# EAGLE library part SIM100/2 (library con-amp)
AMP connector
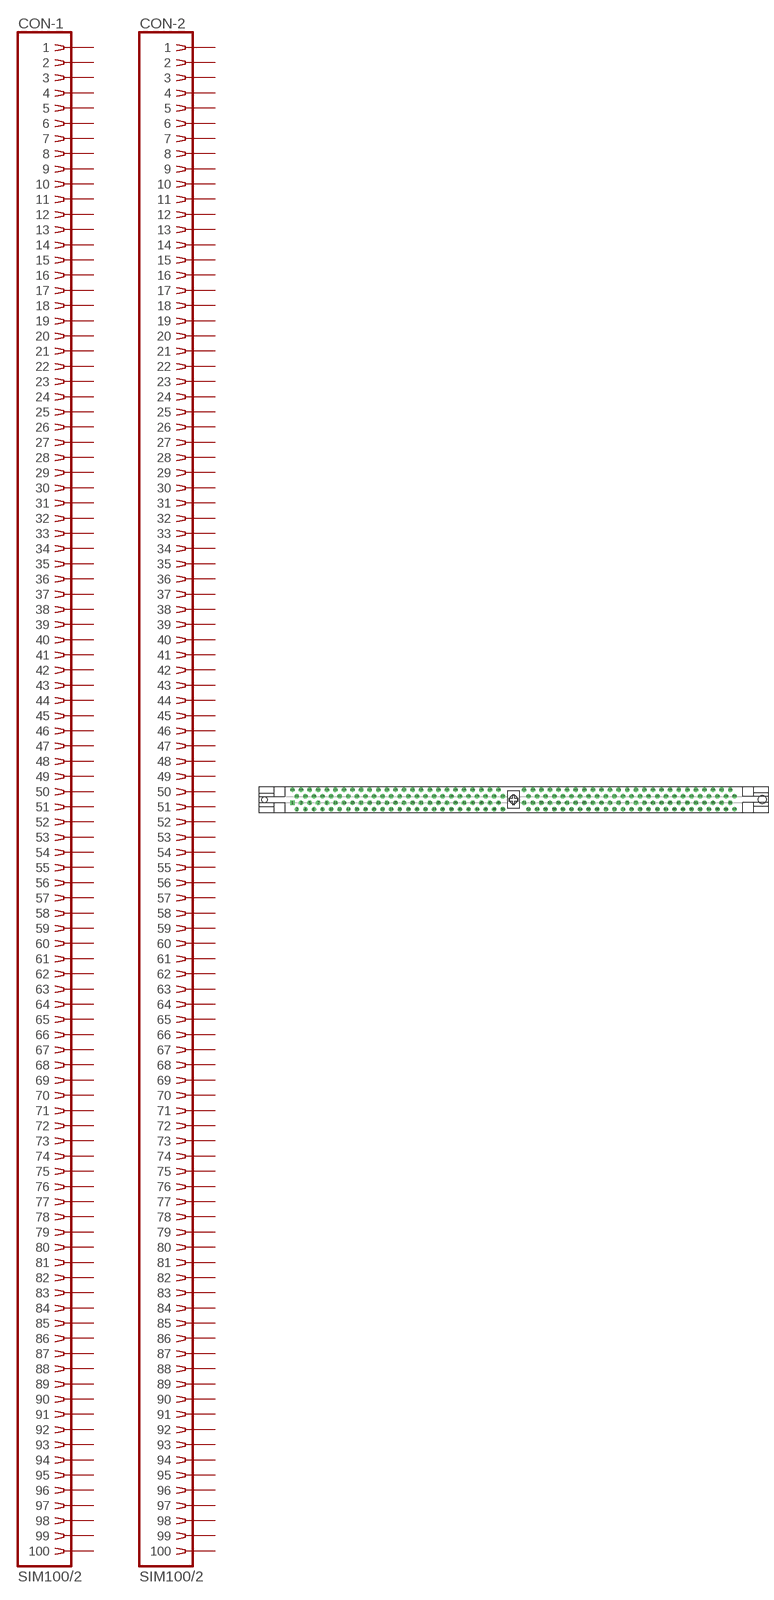
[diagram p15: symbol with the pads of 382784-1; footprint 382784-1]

Designator prefix CON; gates -1=SIMM100 -2=SIMM100

## SIM100/2 (OC_FARNELL: unknown; OC_NEWARK: unknown)  [382784-1]
1  -1:1  pas
2  -1:2  pas
3  -1:3  pas
4  -1:4  pas
5  -1:5  pas
6  -1:6  pas
7  -1:7  pas
8  -1:8  pas
9  -1:9  pas
10  -1:10  pas
11  -1:11  pas
12  -1:12  pas
13  -1:13  pas
14  -1:14  pas
15  -1:15  pas
16  -1:16  pas
17  -1:17  pas
18  -1:18  pas
19  -1:19  pas
20  -1:20  pas
21  -1:21  pas
22  -1:22  pas
23  -1:23  pas
24  -1:24  pas
25  -1:25  pas
26  -1:26  pas
27  -1:27  pas
28  -1:28  pas
29  -1:29  pas
30  -1:30  pas
31  -1:31  pas
32  -1:32  pas
33  -1:33  pas
34  -1:34  pas
35  -1:35  pas
36  -1:36  pas
37  -1:37  pas
38  -1:38  pas
39  -1:39  pas
40  -1:40  pas
41  -1:41  pas
42  -1:42  pas
43  -1:43  pas
44  -1:44  pas
45  -1:45  pas
46  -1:46  pas
47  -1:47  pas
48  -1:48  pas
49  -1:49  pas
50  -1:50  pas
51  -1:51  pas
52  -1:52  pas
53  -1:53  pas
54  -1:54  pas
55  -1:55  pas
56  -1:56  pas
57  -1:57  pas
58  -1:58  pas
59  -1:59  pas
60  -1:60  pas
61  -1:61  pas
62  -1:62  pas
63  -1:63  pas
64  -1:64  pas
65  -1:65  pas
66  -1:66  pas
67  -1:67  pas
68  -1:68  pas
69  -1:69  pas
70  -1:70  pas
71  -1:71  pas
72  -1:72  pas
73  -1:73  pas
74  -1:74  pas
75  -1:75  pas
76  -1:76  pas
77  -1:77  pas
78  -1:78  pas
79  -1:79  pas
80  -1:80  pas
81  -1:81  pas
82  -1:82  pas
83  -1:83  pas
84  -1:84  pas
85  -1:85  pas
86  -1:86  pas
87  -1:87  pas
88  -1:88  pas
89  -1:89  pas
90  -1:90  pas
91  -1:91  pas
92  -1:92  pas
93  -1:93  pas
94  -1:94  pas
95  -1:95  pas
96  -1:96  pas
97  -1:97  pas
98  -1:98  pas
99  -1:99  pas
100  -1:100  pas
101  -2:1  pas
102  -2:2  pas
103  -2:3  pas
104  -2:4  pas
105  -2:5  pas
106  -2:6  pas
107  -2:7  pas
108  -2:8  pas
109  -2:9  pas
110  -2:10  pas
111  -2:11  pas
112  -2:12  pas
113  -2:13  pas
114  -2:14  pas
115  -2:15  pas
116  -2:16  pas
117  -2:17  pas
118  -2:18  pas
119  -2:19  pas
120  -2:20  pas
121  -2:21  pas
122  -2:22  pas
123  -2:23  pas
124  -2:24  pas
125  -2:25  pas
126  -2:26  pas
127  -2:27  pas
128  -2:28  pas
129  -2:29  pas
130  -2:30  pas
131  -2:31  pas
132  -2:32  pas
133  -2:33  pas
134  -2:34  pas
135  -2:35  pas
136  -2:36  pas
137  -2:37  pas
138  -2:38  pas
139  -2:39  pas
140  -2:40  pas
141  -2:41  pas
142  -2:42  pas
143  -2:43  pas
144  -2:44  pas
145  -2:45  pas
146  -2:46  pas
147  -2:47  pas
148  -2:48  pas
149  -2:49  pas
150  -2:50  pas
151  -2:51  pas
152  -2:52  pas
153  -2:53  pas
154  -2:54  pas
155  -2:55  pas
156  -2:56  pas
157  -2:57  pas
158  -2:58  pas
159  -2:59  pas
160  -2:60  pas
161  -2:61  pas
162  -2:62  pas
163  -2:63  pas
164  -2:64  pas
165  -2:65  pas
166  -2:66  pas
167  -2:67  pas
168  -2:68  pas
169  -2:69  pas
170  -2:70  pas
171  -2:71  pas
172  -2:72  pas
173  -2:73  pas
174  -2:74  pas
175  -2:75  pas
176  -2:76  pas
177  -2:77  pas
178  -2:78  pas
179  -2:79  pas
180  -2:80  pas
181  -2:81  pas
182  -2:82  pas
183  -2:83  pas
184  -2:84  pas
185  -2:85  pas
186  -2:86  pas
187  -2:87  pas
188  -2:88  pas
189  -2:89  pas
190  -2:90  pas
191  -2:91  pas
192  -2:92  pas
193  -2:93  pas
194  -2:94  pas
195  -2:95  pas
196  -2:96  pas
197  -2:97  pas
198  -2:98  pas
199  -2:99  pas
200  -2:100  pas

## Footprint 382784-1 (pad centres in mm)
DIMM I Dual Read Out
drill 0.813 square: 1 -65.405,-0.953
drill 0.813 octagon: 2 -64.135,-2.857; 3 -62.865,-0.953; 4 -61.595,-2.857; 5 -60.325,-0.953; 6 -59.055,-2.857; 7 -57.785,-0.953; 8 -56.515,-2.857; 9 -55.245,-0.953; 10 -53.975,-2.857; 11 -52.705,-0.953; 12 -51.435,-2.857; 13 -50.165,-0.953; 14 -48.895,-2.857; 15 -47.625,-0.953; 16 -46.355,-2.857; 17 -45.085,-0.953; 18 -43.815,-2.857; 19 -42.545,-0.953; 20 -41.275,-2.857; 21 -40.005,-0.953; 22 -38.735,-2.857; 23 -37.465,-0.953; 24 -36.195,-2.857; 25 -34.925,-0.953; 26 -33.655,-2.857; 27 -32.385,-0.953; 28 -31.115,-2.857; 29 -29.845,-0.953; 30 -28.575,-2.857; 31 -27.305,-0.953; 32 -26.035,-2.857; 33 -24.765,-0.953; 34 -23.495,-2.857; 35 -22.225,-0.953; 36 -20.955,-2.857; 37 -19.685,-0.953; 38 -18.415,-2.857; 39 -17.145,-0.953; 40 -15.875,-2.857; 41 -14.605,-0.953; 42 -13.335,-2.857; 43 -12.065,-0.953; 44 -10.795,-2.857; 45 -9.525,-0.953; 46 -8.255,-2.857; 47 -6.985,-0.953; 48 -5.715,-2.857; 49 -4.445,-0.953; 50 -3.175,-2.857; 51 3.175,-0.953; 52 4.445,-2.857; 53 5.715,-0.953; 54 6.985,-2.857; 55 8.255,-0.953; 56 9.525,-2.857; 57 10.795,-0.953; 58 12.065,-2.857; 59 13.335,-0.953; 60 14.605,-2.857; 61 15.875,-0.953; 62 17.145,-2.857; 63 18.415,-0.953; 64 19.685,-2.857; 65 20.955,-0.953; 66 22.225,-2.857; 67 23.495,-0.953; 68 24.765,-2.857; 69 26.035,-0.953; 70 27.305,-2.857; 71 28.575,-0.953; 72 29.845,-2.857; 73 31.115,-0.953; 74 32.385,-2.857; 75 33.655,-0.953; 76 34.925,-2.857; 77 36.195,-0.953; 78 37.465,-2.857; 79 38.735,-0.953; 80 40.005,-2.857; 81 41.275,-0.953; 82 42.545,-2.857; 83 43.815,-0.953; 84 45.085,-2.857; 85 46.355,-0.953; 86 47.625,-2.857; 87 48.895,-0.953; 88 50.165,-2.857; 89 51.435,-0.953; 90 52.705,-2.857; 91 53.975,-0.953; 92 55.245,-2.857; 93 56.515,-0.953; 94 57.785,-2.857; 95 59.055,-0.953; 96 60.325,-2.857; 97 61.595,-0.953; 98 62.865,-2.857; 99 64.135,-0.953; 100 65.405,-2.857; 101 -65.405,2.857; 102 -64.135,0.953; 103 -62.865,2.857; 104 -61.595,0.953; 105 -60.325,2.857; 106 -59.055,0.953; 107 -57.785,2.857; 108 -56.515,0.953; 109 -55.245,2.857; 110 -53.975,0.953; 111 -52.705,2.857; 112 -51.435,0.953; 113 -50.165,2.857; 114 -48.895,0.953; 115 -47.625,2.857; 116 -46.355,0.953; 117 -45.085,2.857; 118 -43.815,0.953; 119 -42.545,2.857; 120 -41.275,0.953; 121 -40.005,2.857; 122 -38.735,0.953; 123 -37.465,2.857; 124 -36.195,0.953; 125 -34.925,2.857; 126 -33.655,0.953; 127 -32.385,2.857; 128 -31.115,0.953; 129 -29.845,2.857; 130 -28.575,0.953; 131 -27.305,2.857; 132 -26.035,0.953; 133 -24.765,2.857; 134 -23.495,0.953; 135 -22.225,2.857; 136 -20.955,0.953; 137 -19.685,2.857; 138 -18.415,0.953; 139 -17.145,2.857; 140 -15.875,0.953; 141 -14.605,2.857; 142 -13.335,0.953; 143 -12.065,2.857; 144 -10.795,0.953; 145 -9.525,2.857; 146 -8.255,0.953; 147 -6.985,2.857; 148 -5.715,0.953; 149 -4.445,2.857; 150 -3.175,0.953; 151 3.175,2.857; 152 4.445,0.953; 153 5.715,2.857; 154 6.985,0.953; 155 8.255,2.857; 156 9.525,0.953; 157 10.795,2.857; 158 12.065,0.953; 159 13.335,2.857; 160 14.605,0.953; 161 15.875,2.857; 162 17.145,0.953; 163 18.415,2.857; 164 19.685,0.953; 165 20.955,2.857; 166 22.225,0.953; 167 23.495,2.857; 168 24.765,0.953; 169 26.035,2.857; 170 27.305,0.953; 171 28.575,2.857; 172 29.845,0.953; 173 31.115,2.857; 174 32.385,0.953; 175 33.655,2.857; 176 34.925,0.953; 177 36.195,2.857; 178 37.465,0.953; 179 38.735,2.857; 180 40.005,0.953; 181 41.275,2.857; 182 42.545,0.953; 183 43.815,2.857; 184 45.085,0.953; 185 46.355,2.857; 186 47.625,0.953; 187 48.895,2.857; 188 50.165,0.953; 189 51.435,2.857; 190 52.705,0.953; 191 53.975,2.857; 192 55.245,0.953; 193 56.515,2.857; 194 57.785,0.953; 195 59.055,2.857; 196 60.325,0.953; 197 61.595,2.857; 198 62.865,0.953; 199 64.135,2.857; 200 65.405,0.953
hole 1.575 at -73.66,0
hole 2.362 at 0,0
hole 2.362 at 73.66,0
